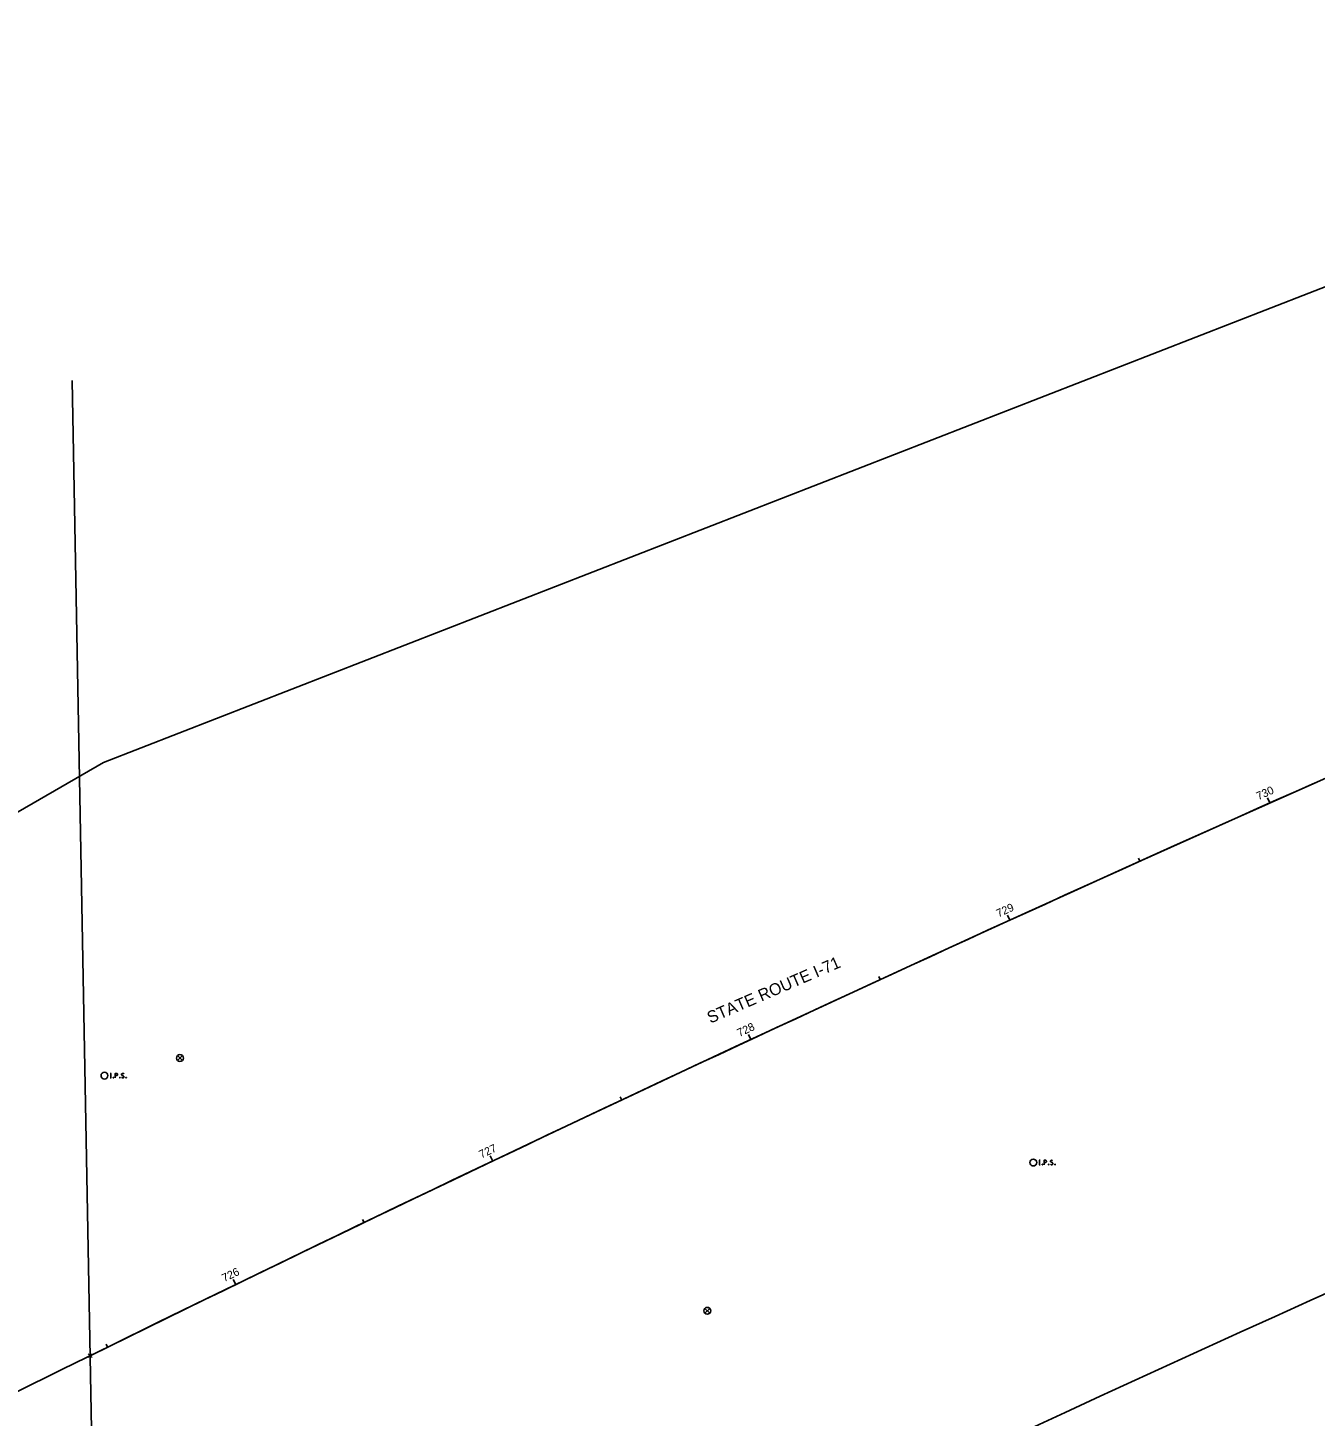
# Model space of a CAD drawing. Extents: x 197895 to 202694, y 454260 to 456995.
# Drawn here: x 201037.3 to 201488.7, y 456508 to 456995 of the extents above; entities that cross this region are included whole.
import ezdxf

# ---------------------------------------------------------------- set-up
doc = ezdxf.new("R2010")
doc.units = 0
for name, color, linetype in [('Default', 7, 'Continuous'), ('DR_X_Elev_Flow', 7, 'Continuous'), ('PM_X_Surveyed_Line', 7, 'Continuous'), ('PV_X_EOP', 7, 'Continuous'), ('PV_X_Shoulder_Aggregate', 7, 'Continuous'), ('SV_X_Control_Cells_Found', 7, 'Continuous'), ('SV_X_Random_Point', 7, 'Continuous'), ('SV_X_Shot_Marker', 7, 'Continuous'), ('SV_X_Top_of_Bank', 7, 'Continuous')]:
    doc.layers.add(name, color=color, linetype=linetype)

msp = doc.modelspace()

# ---------------------------------------------------------------- linework, layer by layer
at = {"layer": 'DR_X_Elev_Flow'}
for p, q in [((201091.53, 456632.81), (201089.84, 456634.5)), ((201089.84, 456632.81), (201091.53, 456634.5)), ((201276.4, 456544.16), (201274.7, 456545.86)), ((201274.7, 456544.16), (201276.4, 456545.86))]:
    msp.add_line(p, q, dxfattribs=at)
for centre in [(201090.69, 456633.65), (201275.55, 456545.01)]:
    msp.add_circle(centre, 1.2, dxfattribs=at)
at = {"layer": 'PM_X_Surveyed_Line'}
msp.add_arc((206475.15, 445510.73), 12112.67, 112.468785, 116.55179, dxfattribs=at)
at = {"layer": 'PV_X_EOP'}
msp.add_line((201073.57, 455742.44), (201052.92, 456871.23), dxfattribs=at)
msp.add_arc((206475.15, 445510.73), 12277.67, 113.962531, 116.175604, dxfattribs=at)
at = {"layer": 'PV_X_Shoulder_Aggregate'}
for p, q in [((201472.8, 456723.12), (201471.99, 456724.94)), ((201427.18, 456702.65), (201426.69, 456703.74)), ((201381.64, 456682), (201380.81, 456683.82)), ((201336.19, 456661.17), (201335.69, 456662.25)), ((201290.83, 456640.14), (201289.98, 456641.96)), ((201245.55, 456618.94), (201245.03, 456620.03)), ((201200.35, 456597.55), (201199.49, 456599.36)), ((201155.24, 456575.98), (201154.72, 456577.06)), ((201110.23, 456554.22), (201109.35, 456556.02)), ((201065.3, 456532.28), (201064.77, 456533.36))]:
    msp.add_line(p, q, dxfattribs=at)
at = {"layer": 'SV_X_Control_Cells_Found'}
msp.add_arc((206475.15, 445510.73), 12277.67, 112.039489, 134.330526, dxfattribs=at)
at = {"layer": 'SV_X_Random_Point'}
for points in [[(201066.23, 456628.28), (201066.58, 456628.28)], [(201066.41, 456626.68), (201066.41, 456628.28)], [(201067.97, 456626.68), (201067.97, 456628.28), (201068.5, 456628.28), (201068.56, 456628.27), (201068.63, 456628.24), (201068.67, 456628.22), (201068.7, 456628.19), (201068.74, 456628.13), (201068.78, 456628.07), (201068.8, 456627.97), (201068.8, 456627.81), (201068.79, 456627.76), (201068.77, 456627.69), (201068.72, 456627.6), (201068.68, 456627.56), (201068.65, 456627.54), (201068.59, 456627.51), (201068.5, 456627.5), (201067.97, 456627.5)], [(201070.98, 456628.17), (201070.96, 456628.19), (201070.93, 456628.22), (201070.83, 456628.26), (201070.71, 456628.28), (201070.62, 456628.28), (201070.59, 456628.28), (201070.44, 456628.24), (201070.32, 456628.17), (201070.24, 456628.07), (201070.22, 456627.97), (201070.22, 456627.89), (201070.24, 456627.79), (201070.33, 456627.7), (201070.94, 456627.32), (201070.99, 456627.27), (201071.02, 456627.22), (201071.04, 456627.15), (201071.04, 456627.07), (201071.03, 456627), (201071.02, 456626.95), (201070.99, 456626.88), (201070.97, 456626.83), (201070.95, 456626.79), (201070.92, 456626.76), (201070.88, 456626.73), (201070.84, 456626.71), (201070.81, 456626.69), (201070.71, 456626.68), (201070.55, 456626.68), (201070.45, 456626.71), (201070.31, 456626.79), (201070.22, 456626.87)], [(201066.23, 456626.68), (201066.58, 456626.68)], [(201067.37, 456626.89), (201067.42, 456626.89), (201067.45, 456626.87), (201067.49, 456626.82), (201067.49, 456626.76), (201067.45, 456626.71), (201067.42, 456626.68), (201067.37, 456626.68), (201067.33, 456626.71), (201067.3, 456626.76), (201067.3, 456626.82), (201067.33, 456626.87), (201067.37, 456626.89)], [(201069.62, 456626.89), (201069.67, 456626.89), (201069.7, 456626.87), (201069.74, 456626.82), (201069.74, 456626.76), (201069.7, 456626.71), (201069.67, 456626.68), (201069.62, 456626.68), (201069.58, 456626.71), (201069.55, 456626.76), (201069.55, 456626.82), (201069.58, 456626.87), (201069.62, 456626.89)], [(201071.8, 456626.89), (201071.85, 456626.89), (201071.89, 456626.87), (201071.92, 456626.82), (201071.92, 456626.76), (201071.89, 456626.71), (201071.85, 456626.68), (201071.8, 456626.68), (201071.76, 456626.71), (201071.73, 456626.76), (201071.73, 456626.82), (201071.76, 456626.87), (201071.8, 456626.89)], [(201391.88, 456597.81), (201392.24, 456597.81)], [(201391.88, 456596.21), (201392.24, 456596.21)], [(201392.06, 456596.21), (201392.06, 456597.81)], [(201393.02, 456596.42), (201393.07, 456596.42), (201393.11, 456596.4), (201393.14, 456596.35), (201393.14, 456596.28), (201393.11, 456596.23), (201393.07, 456596.21), (201393.02, 456596.21), (201392.98, 456596.23), (201392.95, 456596.28), (201392.95, 456596.35), (201392.98, 456596.4), (201393.02, 456596.42)], [(201393.62, 456596.21), (201393.62, 456597.81), (201394.15, 456597.81), (201394.21, 456597.79), (201394.29, 456597.77), (201394.32, 456597.74), (201394.35, 456597.72), (201394.4, 456597.66), (201394.43, 456597.59), (201394.45, 456597.49), (201394.45, 456597.34), (201394.44, 456597.29), (201394.42, 456597.22), (201394.37, 456597.13), (201394.33, 456597.09), (201394.3, 456597.06), (201394.24, 456597.04), (201394.15, 456597.03), (201393.62, 456597.03)], [(201395.27, 456596.42), (201395.32, 456596.42), (201395.35, 456596.4), (201395.39, 456596.35), (201395.39, 456596.28), (201395.35, 456596.23), (201395.32, 456596.21), (201395.27, 456596.21), (201395.23, 456596.23), (201395.2, 456596.28), (201395.2, 456596.35), (201395.23, 456596.4), (201395.27, 456596.42)], [(201396.63, 456597.69), (201396.61, 456597.72), (201396.58, 456597.74), (201396.48, 456597.78), (201396.36, 456597.81), (201396.27, 456597.81), (201396.24, 456597.81), (201396.09, 456597.77), (201395.97, 456597.69), (201395.89, 456597.59), (201395.87, 456597.49), (201395.87, 456597.42), (201395.89, 456597.32), (201395.98, 456597.23), (201396.59, 456596.85), (201396.64, 456596.8), (201396.67, 456596.75), (201396.69, 456596.67), (201396.69, 456596.6), (201396.68, 456596.52), (201396.67, 456596.47), (201396.64, 456596.41), (201396.62, 456596.36), (201396.6, 456596.32), (201396.57, 456596.28), (201396.53, 456596.26), (201396.49, 456596.23), (201396.46, 456596.22), (201396.36, 456596.21), (201396.2, 456596.21), (201396.1, 456596.23), (201395.96, 456596.32), (201395.87, 456596.4)], [(201397.45, 456596.42), (201397.5, 456596.42), (201397.54, 456596.4), (201397.57, 456596.35), (201397.57, 456596.28), (201397.54, 456596.23), (201397.5, 456596.21), (201397.45, 456596.21), (201397.42, 456596.23), (201397.38, 456596.28), (201397.38, 456596.35), (201397.42, 456596.4), (201397.45, 456596.42)]]:
    msp.add_lwpolyline(points, dxfattribs=at)
for centre in [(201064.21, 456627.48), (201389.86, 456597.01)]:
    msp.add_circle(centre, 1.2, dxfattribs=at)
at = {"layer": 'SV_X_Shot_Marker'}
for p, q in [((201058.51, 456528.61), (201059.84, 456529.94)), ((201058.51, 456529.94), (201059.84, 456528.61))]:
    msp.add_line(p, q, dxfattribs=at)
at = {"layer": 'SV_X_Top_of_Bank'}
for p, q in [((201063.88, 456737.31), (201725.54, 456994.98)), ((200677.78, 456514.05), (201063.88, 456737.31))]:
    msp.add_line(p, q, dxfattribs=at)

# ---------------------------------------------------------------- texts
at = {"layer": 'Default'}
msp.add_text('STATE ROUTE I-71', height=4.1667, rotation=23.3989, dxfattribs=at).set_placement((201276.62, 456645.7))
at = {"layer": 'PV_X_Shoulder_Aggregate'}
for s, rotation, p in [('730', 24.0438, (201468.8, 456724.07)), ('729', 24.5105, (201377.67, 456682.94)), ('728', 24.9771, (201286.82, 456641.04)), ('727', 25.4438, (201196.35, 456598.41)), ('726', 25.9105, (201106.21, 456555.05))]:
    msp.add_text(s, height=2.8, rotation=rotation, dxfattribs=at).set_placement(p)

doc.saveas('drawing.dxf')
